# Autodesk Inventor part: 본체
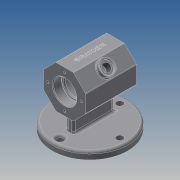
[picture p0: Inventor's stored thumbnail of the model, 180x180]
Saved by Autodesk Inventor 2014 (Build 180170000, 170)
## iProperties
Created: 2021-02
Part Number: 본체
Material: Generic
Document SubType Name: Modeling
Designer: kb542-23
Density: 1 g/cm^3
Appearance: Default
Author: kb542-23
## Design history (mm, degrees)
sketch "스케치1" dims "d0" = 58
  geometry: L1 (12.012, 29)-(29, 12.012); L2 (29, 12.012)-(29, -12.012); L3 (29, -12.012)-(12.012, -29); L4 (12.012, -29)-(-12.012, -29); L5 (-12.012, -29)-(-29, -12.012); L6 (-29, -12.012)-(-29, 12.012); L7 (-29, 12.012)-(-12.012, 29); L8 (-12.012, 29)-(12.012, 29); 4 further points
  constraints: 16 end point, 2 coincident, 2 vertical alignment, 1 midpoint, 19 other
extrude "돌출1" new body sketch "스케치1" stored distance "d2" = 70; taper "d3" = 0 deg
sketch "스케치2"
  geometry: L1 (-35, 12.012)-(-35, -12.012) reference; L2 (35, -12.012)-(35, 12.012) reference; L3 (-35, 0)-(35, 0); L4 (-23, 14)-(-20, 14); L5 (-20, 14)-(-20, 19); L6 (-17, 22)-(17, 22); L7 (20, 14)-(23, 14); L8 (23, 14)-(23, 15.7); L9 (23.3, 16)-(35, 16); L10 (-23.3, 16)-(-35, 16); L11 (-23, 14)-(-23, 15.7); L12 (20, 19)-(20, 14); L13 (-35, 16)-(-35, 0); L14 (35, 0)-(35, 16); A1 r 0.3 centre (-23.3, 15.7) between (-23, 15.7) and (-23.3, 16); A2 r 0.3 centre (23.3, 15.7) between (23.3, 16) and (23, 15.7); A3 r 3 centre (-17, 19) between (-17, 22) and (-20, 19); A4 r 3 centre (17, 19) between (20, 19) and (17, 22); 3 further points
  constraints: 24 end point, 8 point on circle, 8 tangent, 5 point on line, 4 centre point, 3 perpendicular, 2 collinear, 2 equal radius, 2 midpoint, 1 parallel, 1 vertical alignment
  dimensions: "d5" = 32 diameter of L10 L3; "d6" = 28 diameter of L4 L3; "d7" = 44 diameter of L6 L3; "d8" = 28 diameter of L7 L3; "d9" = 32 diameter of L9 L3; "d10" = 12 distance of point (-23, 16) L10.end; "d12" = 12 distance of point (23, 16) L9.end; "d13" = 3 distance of L4.start L4.end; "d14" = 3 distance of L7.start L7.end; "d15" = 0.3 radius of A1; "d16" = 40 distance between parallel lines of L12 L5; "d17" = 3 radius of A3
revolve "회전1" sketch "스케치2" stored, may be unused: angle "d18" = 90 deg
sketch "스케치3"
  geometry: A1 r 23 centre (0, 0) between (0, 23) and (-23, 0); 3 further points
  constraints: 4 point on circle, 1 centre point, 1 coincident
  dimensions: "d19" = 46 diameter of A1
hole "구멍1" sketch "스케치3" at (0, 23), (-23, 0), (0, -23), (23, 0) diameter "d20" = 3.242; stored, may be unused: countersink angle "d24" = 90 deg, drill point angle "d26" = 118 deg; dims "d21" = 8, "d22" = 4, "d23" = 2, "d25" = 10
node "작업 평면1"
sketch "스케치4"
  geometry: C1 r 52 at (0, 0); 1 further point
  constraints: 1 centre point, 1 coincident
  dimensions: "d28" = 104 diameter of C1
extrude "돌출2" join sketch "스케치4" distance "d29" = 10; taper "d30" = 0 deg
sketch "스케치5"
  geometry: A1 r 41 centre (0, 0) between (0, 41) and (-41, 0); 3 further points
  constraints: 4 point on circle, 1 centre point, 1 coincident
  dimensions: "d31" = 82 diameter of A1
hole "구멍2" sketch "스케치5" at (0, 41), (-41, 0), (0, -41), (41, 0) diameter "d32" = 9; stored, may be unused: countersink angle "d36" = 90 deg, drill point angle "d38" = 118 deg; dims "d33" = 9, "d34" = 4, "d35" = 2, "d37" = 10
sketch "스케치6"
  geometry: L1 (5, -28)-(-5, -28); L2 (-5, -28)-(-5, 28); L3 (-5, 28)-(5, 28); L4 (5, 28)-(5, -28); L5 (5, -28)-(-5, 28); L6 (-5, -28)-(5, 28); 1 further point
  constraints: 12 end point, 2 midpoint, 2 parallel, 1 horizontal, 1 perpendicular
  dimensions: "d40" = 10 distance of L2.end L3.end; "d41" = 56 distance of L3.end L1.start
extrude "돌출3" join sketch "스케치6" stored distance "d42" = 10; taper "d43" = 0 deg
node "작업 평면2"
sketch "스케치7"
  geometry: C1 r 10 at (-12.012, 35); 1 further point
  constraints: 1 centre point, 1 coincident
  dimensions: "d45" = 20 diameter of C1
extrude "돌출4" join sketch "스케치7" distance "d46" = 5; taper "d47" = 0 deg
sketch "스케치8"
  geometry: C1 r 10 at (0, 0) reference; C2 r 8 at (0, 0)
  constraints: 1 centre point, 1 coincident
  dimensions: "d48" = 16 diameter of C2
extrude "돌출5" cut sketch "스케치8" distance "d49" = 2; taper "d50" = 0 deg
sketch "스케치9"
  geometry: C1 r 8 at (0, 0) reference; 1 further point
  constraints: 1 coincident
hole "구멍3" sketch "스케치9" at (0, 0) diameter "d51" = 10.917; stored, may be unused: countersink angle "d55" = 90 deg, drill point angle "d57" = 118 deg; dims "d52" = 15, "d53" = 16, "d54" = 19.25, "d56" = 17.25
sketch "스케치10"
  geometry: L1 (-16.988, 0)-(-16.988, -70) reference; L2 (24.024, -70)-(0, -70) reference; 1 further point
  constraints: 1 other
  dimensions: "d58" = 29 distance from line of L1 point (12.012, -35); "d59" = 35 distance from line of point (12.012, -35) L2
feature "엠보싱1" sketch "스케치10" dims "d0" = 58, "d5" = 32, "d6" = 28, "d7" = 44, "d8" = 28, "d9" = 32, "d10" = 12, "d12" = 12, "d13" = 3, "d14" = 3, "d15" = 0.3, "d16" = 40, "d17" = 3, "d60" = 0.5, "d61" = 0
chamfer "모따기1" distance "d62" = 1; stored, may be unused: second distance "d63" = 2, angle "d64" = 45 deg
fillet "모깎기2" dims "d67" = 1, "d68" = 3
node "솔리드1"
mirror "대칭1"
other parameters: "d27" = -62, "d44" = 5
